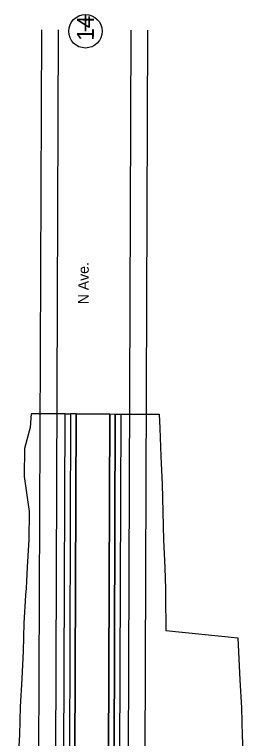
# Model space of a CAD drawing. Extents: x 15359458 to 15360238, y 8797399 to 8799222.
# Drawn here: x 15359880 to 15360044, y 8798704 to 8799222 of the extents above; entities that cross this region are included whole.
import ezdxf

# ---------------------------------------------------------------- set-up
doc = ezdxf.new("R2010")
doc.units = 0
for name, color, linetype in [('Alignment', 7, 'Continuous'), ('PhoTerrainVoid', 7, 'Continuous'), ('TL_Barrier', 7, 'Continuous')]:
    doc.layers.add(name, color=color, linetype=linetype)

msp = doc.modelspace()

# ---------------------------------------------------------------- linework, layer by layer
at = {"layer": 'Alignment'}
for p, q in [((15359898.87, 8799211.58), (15359893.01, 8797661.59)), ((15359910.87, 8799211.53), (15359905.01, 8797661.54)), ((15359962.87, 8799211.33), (15359957.01, 8797661.35)), ((15359974.87, 8799211.29), (15359969.01, 8797661.3))]:
    msp.add_line(p, q, dxfattribs=at)
at = {"layer": 'PhoTerrainVoid'}
for p, q in [((15359930.5, 8799222.49), (15359930.45, 8799210.49)), ((15359930.45, 8799210.49), (15359930.5, 8799222.49)), ((15359914.22, 8798509.74), (15359915.83, 8798936.51)), ((15359915.83, 8798936.51), (15359919.83, 8798936.5)), ((15359919.83, 8798936.5), (15359918.22, 8798509.72)), ((15359919.83, 8798936.5), (15359918.22, 8798509.72)), ((15359923.83, 8798936.48), (15359919.83, 8798936.5)), ((15359923.83, 8798936.48), (15359921.95, 8798438.48)), ((15359921.95, 8798438.48), (15359923.83, 8798936.48)), ((15359921.95, 8798438.48), (15359923.83, 8798936.48)), ((15359923.83, 8798936.48), (15359947.83, 8798936.39)), ((15359945.95, 8798438.39), (15359947.83, 8798936.39)), ((15359945.95, 8798438.39), (15359947.83, 8798936.39)), ((15359947.83, 8798936.39), (15359945.95, 8798438.39)), ((15359947.83, 8798936.39), (15359951.83, 8798936.37)), ((15359951.83, 8798936.37), (15359950.17, 8798497.11)), ((15359950.17, 8798497.11), (15359951.83, 8798936.37)), ((15359951.83, 8798936.37), (15359955.83, 8798936.36)), ((15359955.83, 8798936.36), (15359954.17, 8798497.09))]:
    msp.add_line(p, q, dxfattribs=at)
msp.add_circle((15359930.45, 8799210.49), 12, dxfattribs=at)
at = {"layer": 'TL_Barrier'}
for p, q in [((15359915.83, 8798936.51), (15359891.65, 8798936.6)), ((15359955.83, 8798936.36), (15359983.21, 8798936.26))]:
    msp.add_line(p, q, dxfattribs=at)
for points in [[(15359891.65, 8798936.6), (15359890.77, 8798926.61), (15359886.85, 8798911.62), (15359886.51, 8798891.62), (15359890.22, 8798866.61), (15359889.88, 8798846.61), (15359888.77, 8798826.61), (15359887.88, 8798811.62), (15359887.44, 8798806.62), (15359886.26, 8798786.62), (15359885.96, 8798766.62), (15359884.92, 8798746.63), (15359883.8, 8798726.63), (15359883.22, 8798706.63), (15359881.99, 8798686.64), (15359880.84, 8798666.64), (15359880.09, 8798646.64), (15359879.62, 8798626.65)], [(15359983.21, 8798936.26), (15359983.63, 8798926.25), (15359984.4, 8798906.25), (15359985.46, 8798886.25), (15359985.77, 8798866.25), (15359986.33, 8798846.24), (15359987.33, 8798826.24), (15359987.85, 8798811.24), (15359987.78, 8798806.24), (15359988.01, 8798781.24), (15360039.58, 8798776.04), (15360040.27, 8798761.04), (15360040.92, 8798746.04), (15360042.11, 8798726.03), (15360042.66, 8798706.03), (15360043.62, 8798686.03)]]:
    msp.add_lwpolyline(points, dxfattribs=at)

# ---------------------------------------------------------------- texts
at = {"layer": 'PhoTerrainVoid'}
for s, height, p in [('14', 12, (15359936.43, 8799203.66)), ('N Ave.', 7.5, (15359932.7, 8799015.02))]:
    msp.add_text(s, height=height, rotation=89.7834, dxfattribs=at).set_placement(p)

doc.saveas('drawing.dxf')
